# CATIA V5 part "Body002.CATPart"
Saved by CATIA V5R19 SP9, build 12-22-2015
Part number: Body002
Definition: design
Nomenclature: Body002
Source: Unknown
Bounding box of the stored display mesh (mm): x -56.25 to 47.75, y -35.58 to 36.42, z 0 to 23
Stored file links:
  Z:\charly_robot\Body002.CATPart
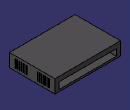
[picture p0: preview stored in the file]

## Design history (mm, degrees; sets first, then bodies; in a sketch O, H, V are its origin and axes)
AxisSystem1: origin (0, 0, 0), X (1, 0, 0), Y (0, 1, 0), Z (0, 0, 1)
Body1 "MANIFOLD_SOLID_BREP #6666" (main body)
  Solid1: solid without history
